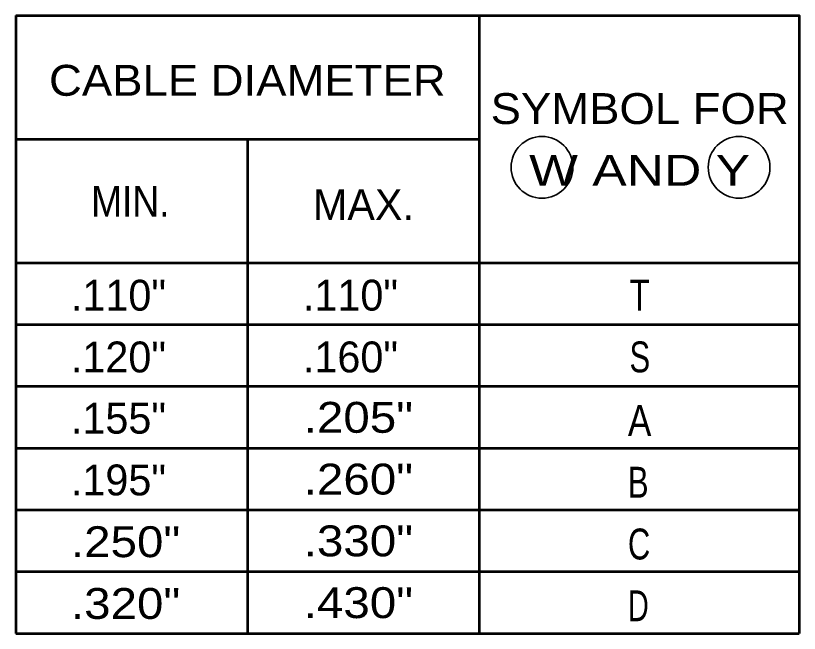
# Model space of a CAD drawing. Extents: x -1 to 679, y 0 to 440.
# Drawn here: x 468.4 to 519.1, y 153 to 193 of the extents above; entities that cross this region are included whole.
import ezdxf
from ezdxf.enums import TextEntityAlignment as Align

# ---------------------------------------------------------------- set-up
doc = ezdxf.new("R2010")
doc.units = 0
doc.header["$LTSCALE"] = 0.8
doc.layers.add('1', color=7, linetype='Continuous', lineweight=53)

msp = doc.modelspace()

# ---------------------------------------------------------------- linework, layer by layer
at = {"layer": '1'}
for p, q in [((468.3979, 193.036), (468.3979, 153.036)), ((498.3979, 193.036), (498.3979, 153.036)), ((468.3979, 185.036), (498.3979, 185.036)), ((483.3979, 185.036), (483.3979, 153.036)), ((468.3979, 177.036), (519.1097, 177.036)), ((468.3979, 173.036), (519.1097, 173.036)), ((468.3979, 169.036), (519.1097, 169.036)), ((468.3979, 165.036), (519.1097, 165.036)), ((468.3979, 161.036), (519.1097, 161.036)), ((468.3979, 157.036), (519.1097, 157.036)), ((468.3979, 153.036), (519.1097, 153.036))]:
    msp.add_line(p, q, dxfattribs=at)
msp.add_lwpolyline([(468.3979, 193.036), (519.1097, 193.036), (519.1097, 153.036)], dxfattribs=at)
at = {"layer": '1', "lineweight": 35}
for centre in [(502.4543, 183.2169), (515.211, 183.2169)]:
    msp.add_circle(centre, 2, dxfattribs=at)

# ---------------------------------------------------------------- texts
at = {"layer": '1'}
for s, width, p in [('CABLE DIAMETER', 1.1, (470.5556, 187.8481)), ('MIN.', 0.9, (473.275, 180.0137)), ('T', 0.8, (508.1193, 173.9392)), ('S', 0.75, (508.1193, 169.9392)), ('.205"', 1.15, (487.0378, 166.0235)), ('A', 0.85, (508.0164, 165.8205)), ('.260"', 1.15, (487.0378, 162.0235)), ('B', 0.75, (508.0164, 161.8205)), ('.250"', 1.15, (471.9726, 157.9691)), ('.330"', 1.15, (487.0378, 158.0235)), ('C', 0.75, (508.0164, 157.8205)), ('.320"', 1.15, (471.9726, 153.9691)), ('.430"', 1.15, (487.0378, 154.0235)), ('D', 0.7, (508.0164, 153.8205))]:
    msp.add_text(s, height=2, dxfattribs=dict(at, width=width)).set_placement(p)
for s, width, p in [('SYMBOL FOR', 1.1, (508.7767, 186.019)), ('W AND Y', 1.25, (508.7767, 182.019))]:
    msp.add_text(s, height=2, dxfattribs=dict(at, width=width)).set_placement(p, align=Align.CENTER)
for s, p in [('MAX.', (487.6332, 179.7961)), ('.110"', (471.9726, 173.9333)), ('.110"', (486.9864, 173.9362)), ('.120"', (471.9726, 169.9333)), ('.160"', (486.9864, 169.9362)), ('.155"', (471.9726, 165.9691)), ('.195"', (471.9726, 161.9691))]:
    msp.add_text(s, height=2, dxfattribs=at).set_placement(p)

doc.saveas('drawing.dxf')
